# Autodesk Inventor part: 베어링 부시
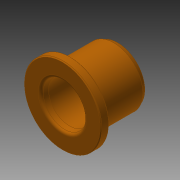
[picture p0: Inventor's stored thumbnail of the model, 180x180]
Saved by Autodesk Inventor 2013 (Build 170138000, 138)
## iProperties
Created: 2022-03
Part Number: 베어링 부시
Material: 황동, 연질
Document SubType Name: Modeling
Designer: mdu-01
Density: 1 g/cm^3
Author: mdu-01
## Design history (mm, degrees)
sketch "스케치1"
  geometry: L1 (0, 0)-(0, -20); L2 (7.941, 0)-(14, 0); L3 (14, 0)-(14, -3); L4 (14, -3)-(10.5, -3); L5 (10.5, -3)-(10.5, -18.6); L6 (9.844, -20)-(7.606, -20); L7 (7.5, -2.5)-(7.5, -19.4); L8 (7.5, -2.5)-(7.941, 0); L9 (7.5, -19.4)-(7.606, -20); L10 (10.5, -18.6)-(9.844, -20)
  constraints: 20 end point, 3 perpendicular, 2 horizontal alignment, 2 parallel, 1 horizontal, 1 vertical
  dimensions: "d0" = 21 diameter of L5 L1; "d2" = 28 diameter of L3 L1; "d3" = 20 distance of L1.start L1.end; "d4" = 3 distance of L2.end L3.end; "d5" = 15 diameter of L7 L1; "d6" = 10 deg angle of L7 L9; "d7" = 0.6 distance from line of L7.end L6; "d8" = 1.4 vertical distance of L5.end L6.start; "d9" = 25.0978 deg angle of L5 L10; "d10" = 10 deg angle of L7 L8; "d11" = 2.5 vertical distance of L7.start L2.start
revolve "회전1" sketch "스케치1" stored, may be unused: angle "d12" = 90 deg
chamfer "모따기1" distance "d13" = 0.3; stored, may be unused: second distance "d14" = 2, angle "d15" = 45 deg
fillet "모깎기1" dims "d16" = 0.3, "d17" = 1
node "솔리드1"
